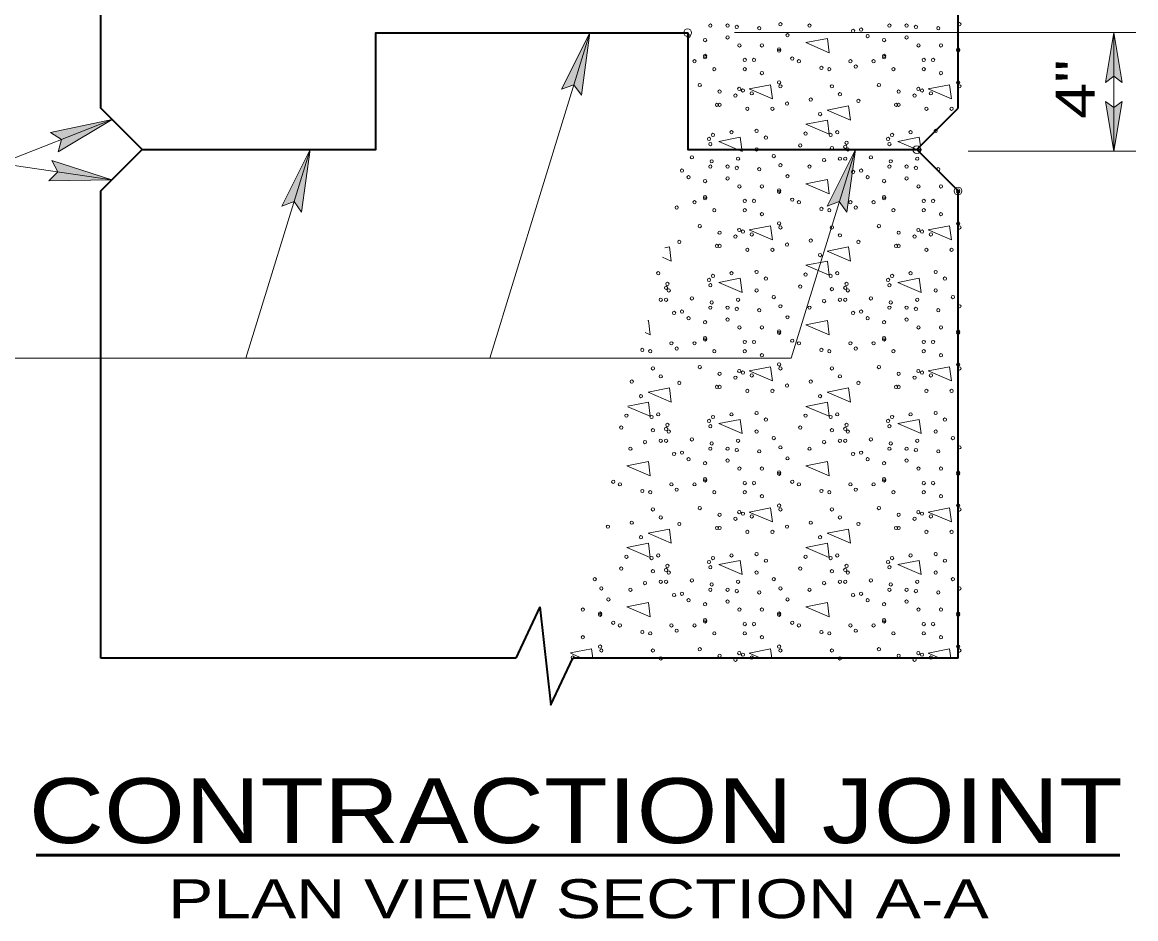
# Model space of a CAD drawing. Extents: x -43.06 to -36.2, y -1.41 to 7.25.
# Drawn here: x -41.643 to -39.928, y 4.85 to 6.232 of the extents above; entities that cross this region are included whole.
import ezdxf
from ezdxf.enums import TextEntityAlignment as Align

# ---------------------------------------------------------------- set-up
doc = ezdxf.new("R2010")
doc.units = 0
doc.header["$LTSCALE"] = 0.024
doc.header["$PDMODE"] = 32
doc.header["$PDSIZE"] = 0.012
for name, color, linetype, lineweight in [('1', 7, 'Continuous', 35), ('10', 7, 'Continuous', 13), ('12', 7, 'Continuous', 53), ('6', 7, 'Continuous', 13)]:
    doc.layers.add(name, color=color, linetype=linetype, lineweight=lineweight)

msp = doc.modelspace()

# ---------------------------------------------------------------- hatches: boundary and pattern name
at = {"layer": '10'}
for points in [[(-40.78142, 6.11917), (-40.76858, 6.21567), (-40.81208, 6.1285), (-40.79325, 6.13533)], [(-39.94858, 6.13917), (-39.96125, 6.216), (-39.97408, 6.13917), (-39.96125, 6.14867)], [(-39.94858, 6.10983), (-39.96125, 6.033), (-39.97408, 6.10983), (-39.96125, 6.10017)], [(-41.50408, 6.08167), (-41.58758, 6.03183), (-41.58225, 6.05117), (-41.59925, 6.06167)], [(-41.19942, 6.0355), (-41.21242, 5.939), (-41.22408, 5.95533), (-41.24292, 5.9485)], [(-40.35958, 6.0355), (-40.37258, 5.939), (-40.38442, 5.95533), (-40.40325, 5.9485)], [(-41.50458, 5.98883), (-41.59725, 6.01883), (-41.58775, 6.00117), (-41.60192, 5.98717)]]:
    msp.add_hatch(color=256, dxfattribs=at).paths.add_polyline_path(points)

# ---------------------------------------------------------------- linework, layer by layer
at = {"layer": '1'}
for p, q in [((-41.52158, 6.09917), (-41.52158, 6.76683)), ((-40.20142, 6.09917), (-40.20142, 6.76583)), ((-40.26492, 6.0355), (-40.20142, 6.09917)), ((-40.20142, 5.97183), (-40.26492, 6.0355)), ((-40.20142, 5.25183), (-40.20142, 5.97183))]:
    msp.add_line(p, q, dxfattribs=at)
for points in [[(-41.45792, 6.0355), (-41.09792, 6.0355), (-41.09792, 6.21567), (-40.61775, 6.21567)], [(-40.61775, 6.21567), (-40.61775, 6.0355), (-40.25775, 6.0355)], [(-41.52158, 5.25183), (-41.52158, 5.97183), (-41.45792, 6.0355), (-41.52158, 6.09917)]]:
    msp.add_lwpolyline(points, dxfattribs=at)
at = {"layer": '10'}
for p, q in [((-40.92258, 5.71433), (-40.76858, 6.21567)), ((-40.81208, 6.1285), (-40.76858, 6.21567)), ((-40.78142, 6.11917), (-40.76858, 6.21567)), ((-39.97408, 6.13917), (-39.96125, 6.216)), ((-39.96125, 6.033), (-39.96125, 6.216)), ((-39.94858, 6.13917), (-39.96125, 6.216)), ((-39.97408, 6.13917), (-39.96125, 6.14867)), ((-39.94858, 6.13917), (-39.96125, 6.14867)), ((-40.81208, 6.1285), (-40.79325, 6.13533)), ((-40.78142, 6.11917), (-40.79325, 6.13533)), ((-39.97408, 6.10983), (-39.96125, 6.033)), ((-39.97408, 6.10983), (-39.96125, 6.10017)), ((-39.94858, 6.10983), (-39.96125, 6.033)), ((-39.94858, 6.10983), (-39.96125, 6.10017)), ((-41.67608, 6.01433), (-41.50408, 6.08167)), ((-41.59925, 6.06167), (-41.50408, 6.08167)), ((-41.58758, 6.03183), (-41.50408, 6.08167)), ((-41.59925, 6.06167), (-41.58225, 6.05117)), ((-41.58758, 6.03183), (-41.58225, 6.05117)), ((-41.29825, 5.71433), (-41.19942, 6.0355)), ((-41.24292, 5.9485), (-41.19942, 6.0355)), ((-41.21242, 5.939), (-41.19942, 6.0355)), ((-40.45842, 5.71433), (-40.35958, 6.0355)), ((-40.40325, 5.9485), (-40.35958, 6.0355)), ((-40.37258, 5.939), (-40.35958, 6.0355)), ((-40.18575, 6.033), (-39.92775, 6.033)), ((-41.67608, 6.01433), (-41.50458, 5.98883)), ((-41.59725, 6.01883), (-41.50458, 5.98883)), ((-41.59725, 6.01883), (-41.58775, 6.00117)), ((-41.60192, 5.98717), (-41.58775, 6.00117)), ((-41.60192, 5.98717), (-41.50458, 5.98883)), ((-41.24292, 5.9485), (-41.22408, 5.95533)), ((-41.21242, 5.939), (-41.22408, 5.95533)), ((-40.40325, 5.9485), (-40.38442, 5.95533)), ((-40.37258, 5.939), (-40.38442, 5.95533)), ((-41.76292, 5.71433), (-41.29825, 5.71433)), ((-41.30158, 5.71433), (-40.91175, 5.71433)), ((-40.92258, 5.71433), (-40.45842, 5.71433))]:
    msp.add_line(p, q, dxfattribs=at)
at = {"layer": '10', "lineweight": 35}
for p, q in [((-40.84558, 5.33083), (-40.88242, 5.25183)), ((-40.88242, 5.25183), (-41.52158, 5.25183)), ((-40.20142, 5.25183), (-40.79458, 5.25183))]:
    msp.add_line(p, q, dxfattribs=at)
at = {"layer": '10'}
for points in [[(-40.78142, 6.11917), (-40.76858, 6.21567), (-40.81208, 6.1285), (-40.79325, 6.13533)], [(-39.94858, 6.13917), (-39.96125, 6.216), (-39.97408, 6.13917), (-39.96125, 6.14867)], [(-39.94858, 6.10983), (-39.96125, 6.033), (-39.97408, 6.10983), (-39.96125, 6.10017)], [(-41.50408, 6.08167), (-41.58758, 6.03183), (-41.58225, 6.05117), (-41.59925, 6.06167)], [(-41.19942, 6.0355), (-41.21242, 5.939), (-41.22408, 5.95533), (-41.24292, 5.9485)], [(-40.35958, 6.0355), (-40.37258, 5.939), (-40.38442, 5.95533), (-40.40325, 5.9485)], [(-41.50458, 5.98883), (-41.59725, 6.01883), (-41.58775, 6.00117), (-41.60192, 5.98717)]]:
    msp.add_lwpolyline(points, close=True, dxfattribs=at)
msp.add_lwpolyline([(-40.54575, 6.216), (-40.10742, 6.216), (-39.92775, 6.216)], dxfattribs=at)
at = {"layer": '10', "lineweight": 35}
msp.add_lwpolyline([(-40.84558, 5.33083), (-40.82875, 5.17983), (-40.79458, 5.25183)], dxfattribs=at)
at = {"layer": '12'}
msp.add_line((-41.62142, 4.94817), (-39.95208, 4.94817), dxfattribs=at)
at = {"layer": '6'}
for p, q in [((-40.26492, 6.0355), (-40.29425, 6.04817)), ((-40.78075, 5.25183), (-40.79858, 5.2595)), ((-40.50492, 5.25183), (-40.52325, 5.25967)), ((-40.22925, 5.25183), (-40.24758, 5.25967))]:
    msp.add_line(p, q, dxfattribs=at)
for points in [[(-40.43575, 6.20033), (-40.40258, 6.20683), (-40.39975, 6.18483)], [(-40.52325, 6.129), (-40.49025, 6.1355), (-40.48742, 6.11367)], [(-40.24758, 6.129), (-40.21442, 6.1355), (-40.21158, 6.11367)], [(-40.40325, 6.0965), (-40.37008, 6.103), (-40.36725, 6.081)], [(-40.43575, 6.0745), (-40.40258, 6.081), (-40.39975, 6.05917)], [(-40.57008, 6.04817), (-40.53708, 6.0545), (-40.53408, 6.03267)], [(-40.43575, 5.983), (-40.40258, 5.9895), (-40.39975, 5.9675)], [(-40.52325, 5.91167), (-40.49025, 5.91817), (-40.48742, 5.89633)], [(-40.24758, 5.91167), (-40.21442, 5.91817), (-40.21158, 5.89633)], [(-40.40325, 5.87917), (-40.37008, 5.8855), (-40.36725, 5.86367)], [(-40.43575, 5.85717), (-40.40258, 5.86367), (-40.39975, 5.84183)], [(-40.57008, 5.83067), (-40.53708, 5.83717), (-40.53408, 5.81533)], [(-40.29425, 5.83067), (-40.26125, 5.83717), (-40.25842, 5.81533)], [(-40.43575, 5.76567), (-40.40258, 5.772), (-40.39975, 5.75017)], [(-40.52325, 5.69433), (-40.49025, 5.70083), (-40.48742, 5.679)], [(-40.24758, 5.69433), (-40.21442, 5.70083), (-40.21158, 5.679)], [(-40.67892, 5.66167), (-40.64592, 5.66817), (-40.64308, 5.64633)], [(-40.40325, 5.66167), (-40.37008, 5.66817), (-40.36725, 5.64633)], [(-40.43575, 5.63983), (-40.40258, 5.64633), (-40.39975, 5.6245)], [(-40.57008, 5.61333), (-40.53708, 5.61983), (-40.53408, 5.598)], [(-40.29425, 5.61333), (-40.26125, 5.61983), (-40.25842, 5.598)], [(-40.71158, 5.54817), (-40.67842, 5.55467), (-40.67558, 5.53283)], [(-40.43575, 5.54817), (-40.40258, 5.55467), (-40.39975, 5.53283)], [(-40.52325, 5.477), (-40.49025, 5.4835), (-40.48742, 5.46167)], [(-40.24758, 5.477), (-40.21442, 5.4835), (-40.21158, 5.46167)], [(-40.67892, 5.44433), (-40.64592, 5.45083), (-40.64308, 5.429)], [(-40.40325, 5.44433), (-40.37008, 5.45083), (-40.36725, 5.429)], [(-40.71158, 5.4225), (-40.67842, 5.429), (-40.67558, 5.40717)], [(-40.43575, 5.4225), (-40.40258, 5.429), (-40.39975, 5.40717)], [(-40.57008, 5.396), (-40.53708, 5.4025), (-40.53408, 5.38067)], [(-40.29425, 5.396), (-40.26125, 5.4025), (-40.25842, 5.38067)], [(-40.71158, 5.33083), (-40.67842, 5.33733), (-40.67558, 5.3155)], [(-40.43575, 5.33083), (-40.40258, 5.33733), (-40.39975, 5.3155)]]:
    msp.add_lwpolyline(points, close=True, dxfattribs=at)
for points in [[(-40.29425, 6.04817), (-40.26125, 6.0545), (-40.25942, 6.04117)], [(-40.65308, 5.88417), (-40.64592, 5.8855), (-40.64308, 5.86367), (-40.65642, 5.8695)], [(-40.67925, 5.772), (-40.67842, 5.772), (-40.67558, 5.75017), (-40.68342, 5.75367)], [(-40.70992, 5.64017), (-40.67842, 5.64633), (-40.67558, 5.6245), (-40.71008, 5.63933)], [(-40.79842, 5.25983), (-40.76608, 5.26617), (-40.76408, 5.25183)], [(-40.52325, 5.25967), (-40.49025, 5.26617), (-40.48842, 5.25183)], [(-40.24758, 5.25967), (-40.21442, 5.26617), (-40.21258, 5.25183)]]:
    msp.add_lwpolyline(points, dxfattribs=at)
for centre in [(-40.58293, 6.22667), (-40.55644, 6.22667), (-40.5422, 6.22463), (-40.47503, 6.22872), (-40.43022, 6.22667), (-40.30712, 6.22667), (-40.28064, 6.22667), (-40.2664, 6.22463), (-40.19923, 6.22872), (-40.61645, 6.21039), (-40.55644, 6.20835), (-40.5076, 6.22259), (-40.46411, 6.21179), (-40.36305, 6.21851), (-40.35081, 6.22055), (-40.34065, 6.21039), (-40.28064, 6.20835), (-40.23179, 6.22259), (-40.59105, 6.20427), (-40.53812, 6.19611), (-40.50351, 6.19611), (-40.47703, 6.19003), (-40.31524, 6.20427), (-40.26232, 6.19611), (-40.22771, 6.19611), (-40.20123, 6.19003), (-40.60733, 6.17171), (-40.59105, 6.17983), (-40.59105, 6.17779), (-40.53, 6.17375), (-40.51572, 6.17375), (-40.47703, 6.18799), (-40.45671, 6.17575), (-40.44651, 6.17171), (-40.36709, 6.17171), (-40.33153, 6.17171), (-40.31524, 6.17983), (-40.31524, 6.17779), (-40.2542, 6.17375), (-40.23991, 6.17375), (-40.20123, 6.18799), (-40.57681, 6.15946), (-40.53, 6.15946), (-40.4119, 6.1615), (-40.3997, 6.15946), (-40.35897, 6.16354), (-40.301, 6.15946), (-40.2542, 6.15946), (-40.50351, 6.15338), (-40.47703, 6.1391), (-40.22771, 6.15338), (-40.20123, 6.1391), (-40.59921, 6.13506), (-40.56869, 6.12486), (-40.53836, 6.12902), (-40.53272, 6.12658), (-40.51908, 6.12222), (-40.47503, 6.13302), (-40.39562, 6.13302), (-40.38342, 6.12078), (-40.32341, 6.13506), (-40.29288, 6.12486), (-40.26256, 6.12902), (-40.25692, 6.12658), (-40.24327, 6.12222), (-40.19923, 6.13302), (-40.57273, 6.1045), (-40.56869, 6.1045), (-40.54424, 6.11878), (-40.46483, 6.10654), (-40.42818, 6.11266), (-40.35489, 6.11062), (-40.29692, 6.1045), (-40.29288, 6.1045), (-40.26844, 6.11878), (-40.52592, 6.09841), (-40.48723, 6.09841), (-40.41394, 6.09025), (-40.25011, 6.09841), (-40.21143, 6.09841), (-40.58497, 6.05205), (-40.57885, 6.05817), (-40.55036, 6.06225), (-40.51168, 6.06429), (-40.49739, 6.05409), (-40.43634, 6.06021), (-40.39766, 6.05817), (-40.38746, 6.06225), (-40.30916, 6.05205), (-40.30304, 6.05817), (-40.27456, 6.06225), (-40.23587, 6.06429), (-40.58293, 6.04393), (-40.51168, 6.03576), (-40.44447, 6.04189), (-40.39562, 6.0378), (-40.37525, 6.03985), (-40.37321, 6.04597), (-40.37117, 6.03576), (-40.30712, 6.04393), (-40.61141, 6.02356), (-40.58089, 6.01744), (-40.54016, 6.02152), (-40.48519, 6.0256), (-40.40782, 6.01948), (-40.38342, 6.02152), (-40.37525, 6.02152), (-40.33561, 6.02356), (-40.30508, 6.01744), (-40.26436, 6.02152), (-40.62661, 6.0032), (-40.58293, 6.00932), (-40.55644, 6.00932), (-40.5422, 6.00728), (-40.5076, 6.00524), (-40.47503, 6.01136), (-40.43022, 6.00932), (-40.36305, 6.00116), (-40.35081, 6.0032), (-40.30712, 6.00932), (-40.28064, 6.00932), (-40.2664, 6.00728), (-40.23179, 6.00524), (-40.61645, 5.99304), (-40.59105, 5.98692), (-40.55644, 5.991), (-40.46411, 5.99444), (-40.34065, 5.99304), (-40.31524, 5.98692), (-40.28064, 5.991), (-40.53812, 5.97876), (-40.50351, 5.97876), (-40.47703, 5.97267), (-40.47703, 5.97063), (-40.26232, 5.97876), (-40.22771, 5.97876), (-40.20123, 5.97267), (-40.20123, 5.97063), (-40.60733, 5.95435), (-40.59105, 5.96247), (-40.59105, 5.96043), (-40.53, 5.95639), (-40.51572, 5.95639), (-40.45671, 5.95839), (-40.44651, 5.95435), (-40.36709, 5.95435), (-40.33153, 5.95435), (-40.31524, 5.96247), (-40.31524, 5.96043), (-40.2542, 5.95639), (-40.23991, 5.95639), (-40.63478, 5.94619), (-40.57681, 5.94211), (-40.53, 5.94211), (-40.50351, 5.93603), (-40.4119, 5.94415), (-40.3997, 5.94211), (-40.35897, 5.94619), (-40.301, 5.94211), (-40.2542, 5.94211), (-40.22771, 5.93603), (-40.59921, 5.91771), (-40.47703, 5.92175), (-40.47503, 5.91567), (-40.39562, 5.91567), (-40.32341, 5.91771), (-40.20123, 5.92175), (-40.19923, 5.91567), (-40.56869, 5.9075), (-40.54424, 5.90142), (-40.53836, 5.91166), (-40.53272, 5.90922), (-40.51908, 5.90486), (-40.38342, 5.90342), (-40.29288, 5.9075), (-40.26844, 5.90142), (-40.26256, 5.91166), (-40.25692, 5.90922), (-40.24327, 5.90486), (-40.6307, 5.89326), (-40.57273, 5.88714), (-40.56869, 5.88714), (-40.52592, 5.88106), (-40.48723, 5.88106), (-40.46483, 5.88918), (-40.42818, 5.8953), (-40.35489, 5.89326), (-40.29692, 5.88714), (-40.29288, 5.88714), (-40.25011, 5.88106), (-40.21143, 5.88106), (-40.41394, 5.8729), (-40.51168, 5.84693), (-40.23587, 5.84693), (-40.66326, 5.84489), (-40.64902, 5.82861), (-40.58497, 5.83469), (-40.57885, 5.84081), (-40.55036, 5.84489), (-40.49739, 5.83673), (-40.43634, 5.84285), (-40.39766, 5.84081), (-40.38746, 5.84489), (-40.37321, 5.82861), (-40.30916, 5.83469), (-40.30304, 5.84081), (-40.27456, 5.84489), (-40.22159, 5.83673), (-40.65106, 5.82249), (-40.64698, 5.81841), (-40.58293, 5.82657), (-40.51168, 5.81841), (-40.44447, 5.82453), (-40.39562, 5.82045), (-40.37525, 5.82249), (-40.37117, 5.81841), (-40.30712, 5.82657), (-40.23587, 5.81841), (-40.65922, 5.80417), (-40.65106, 5.80417), (-40.61141, 5.80621), (-40.58089, 5.80009), (-40.54016, 5.80417), (-40.48519, 5.80825), (-40.40782, 5.80213), (-40.38342, 5.80417), (-40.37525, 5.80417), (-40.33561, 5.80621), (-40.30508, 5.80009), (-40.26436, 5.80417), (-40.20939, 5.80825), (-40.63886, 5.7838), (-40.62661, 5.78584), (-40.58293, 5.79197), (-40.55644, 5.79197), (-40.5422, 5.78993), (-40.5076, 5.78788), (-40.47503, 5.79401), (-40.46411, 5.77708), (-40.43022, 5.79197), (-40.36305, 5.7838), (-40.35081, 5.78584), (-40.30712, 5.79197), (-40.28064, 5.79197), (-40.2664, 5.78993), (-40.23179, 5.78788), (-40.19923, 5.79401), (-40.61645, 5.77568), (-40.59105, 5.76956), (-40.55644, 5.77364), (-40.53812, 5.7614), (-40.50351, 5.7614), (-40.34065, 5.77568), (-40.31524, 5.76956), (-40.28064, 5.77364), (-40.26232, 5.7614), (-40.22771, 5.7614), (-40.59105, 5.74512), (-40.59105, 5.74308), (-40.47703, 5.75532), (-40.47703, 5.75328), (-40.31524, 5.74512), (-40.31524, 5.74308), (-40.20123, 5.75532), (-40.20123, 5.75328), (-40.6877, 5.72679), (-40.6429, 5.737), (-40.63478, 5.72884), (-40.60733, 5.737), (-40.53, 5.73904), (-40.51572, 5.73904), (-40.45671, 5.74104), (-40.44651, 5.737), (-40.4119, 5.72679), (-40.36709, 5.737), (-40.35897, 5.72884), (-40.33153, 5.737), (-40.2542, 5.73904), (-40.23991, 5.73904), (-40.6755, 5.72475), (-40.57681, 5.72475), (-40.53, 5.72475), (-40.50351, 5.71867), (-40.3997, 5.72475), (-40.301, 5.72475), (-40.2542, 5.72475), (-40.22771, 5.71867), (-40.67142, 5.69831), (-40.59921, 5.70035), (-40.53836, 5.69431), (-40.53272, 5.69187), (-40.47703, 5.70439), (-40.47503, 5.69831), (-40.39562, 5.69831), (-40.32341, 5.70035), (-40.26256, 5.69431), (-40.25692, 5.69187), (-40.20123, 5.70439), (-40.19923, 5.69831), (-40.70399, 5.67795), (-40.65922, 5.68607), (-40.6307, 5.67591), (-40.56869, 5.69015), (-40.54424, 5.68407), (-40.51908, 5.68751), (-40.42818, 5.67795), (-40.38342, 5.68607), (-40.35489, 5.67591), (-40.29288, 5.69015), (-40.26844, 5.68407), (-40.24327, 5.68751), (-40.57273, 5.66979), (-40.56869, 5.66979), (-40.52592, 5.6637), (-40.48723, 5.6637), (-40.46483, 5.67183), (-40.29692, 5.66979), (-40.29288, 5.66979), (-40.25011, 5.6637), (-40.21143, 5.6637), (-40.68974, 5.65554), (-40.41394, 5.65554), (-40.71215, 5.6255), (-40.67346, 5.62346), (-40.66326, 5.62754), (-40.57885, 5.62346), (-40.55036, 5.62754), (-40.51168, 5.62958), (-40.43634, 5.6255), (-40.39766, 5.62346), (-40.38746, 5.62754), (-40.30304, 5.62346), (-40.27456, 5.62754), (-40.23587, 5.62958), (-40.72027, 5.60718), (-40.64902, 5.61126), (-40.58497, 5.61734), (-40.58293, 5.60922), (-40.49739, 5.61938), (-40.44447, 5.60718), (-40.37321, 5.61126), (-40.30916, 5.61734), (-40.30712, 5.60922), (-40.22159, 5.61938), (-40.67142, 5.6031), (-40.65106, 5.60514), (-40.64698, 5.60105), (-40.61141, 5.58885), (-40.51168, 5.60105), (-40.48519, 5.59089), (-40.39562, 5.6031), (-40.37525, 5.60514), (-40.37117, 5.60105), (-40.33561, 5.58885), (-40.23587, 5.60105), (-40.20939, 5.59089), (-40.70603, 5.57461), (-40.68362, 5.58477), (-40.65922, 5.58681), (-40.65106, 5.58681), (-40.58293, 5.57461), (-40.58089, 5.58273), (-40.55644, 5.57461), (-40.5422, 5.57257), (-40.54016, 5.58681), (-40.47503, 5.57665), (-40.43022, 5.57461), (-40.40782, 5.58477), (-40.38342, 5.58681), (-40.37525, 5.58681), (-40.30712, 5.57461), (-40.30508, 5.58273), (-40.28064, 5.57461), (-40.2664, 5.57257), (-40.26436, 5.58681), (-40.19923, 5.57665), (-40.63886, 5.56645), (-40.62661, 5.56849), (-40.61645, 5.55833), (-40.55644, 5.55629), (-40.5076, 5.57053), (-40.46411, 5.55973), (-40.36305, 5.56645), (-40.35081, 5.56849), (-40.34065, 5.55833), (-40.28064, 5.55629), (-40.23179, 5.57053), (-40.59105, 5.55221), (-40.53812, 5.54405), (-40.50351, 5.54405), (-40.47703, 5.53796), (-40.31524, 5.55221), (-40.26232, 5.54405), (-40.22771, 5.54405), (-40.20123, 5.53796), (-40.73251, 5.52368), (-40.59105, 5.52776), (-40.59105, 5.52572), (-40.53, 5.52168), (-40.51572, 5.52168), (-40.47703, 5.53592), (-40.45671, 5.52368), (-40.31524, 5.52776), (-40.31524, 5.52572), (-40.2542, 5.52168), (-40.23991, 5.52168), (-40.20123, 5.53592), (-40.72231, 5.51964), (-40.6877, 5.50944), (-40.6755, 5.5074), (-40.6429, 5.51964), (-40.63478, 5.51148), (-40.60733, 5.51964), (-40.57681, 5.5074), (-40.53, 5.5074), (-40.44651, 5.51964), (-40.4119, 5.50944), (-40.3997, 5.5074), (-40.36709, 5.51964), (-40.35897, 5.51148), (-40.33153, 5.51964), (-40.301, 5.5074), (-40.2542, 5.5074), (-40.50351, 5.50132), (-40.47703, 5.48704), (-40.22771, 5.50132), (-40.20123, 5.48704), (-40.67142, 5.48096), (-40.65922, 5.46871), (-40.59921, 5.483), (-40.56869, 5.47279), (-40.53836, 5.47695), (-40.53272, 5.47451), (-40.51908, 5.47015), (-40.47503, 5.48096), (-40.39562, 5.48096), (-40.38342, 5.46871), (-40.32341, 5.483), (-40.29288, 5.47279), (-40.26256, 5.47695), (-40.25692, 5.47451), (-40.24327, 5.47015), (-40.19923, 5.48096), (-40.74063, 5.45447), (-40.70399, 5.46059), (-40.6307, 5.45855), (-40.57273, 5.45243), (-40.56869, 5.45243), (-40.54424, 5.46671), (-40.46483, 5.45447), (-40.42818, 5.46059), (-40.35489, 5.45855), (-40.29692, 5.45243), (-40.29288, 5.45243), (-40.26844, 5.46671), (-40.68974, 5.43819), (-40.52592, 5.44635), (-40.48723, 5.44635), (-40.41394, 5.43819), (-40.25011, 5.44635), (-40.21143, 5.44635), (-40.71215, 5.40814), (-40.67346, 5.4061), (-40.66326, 5.41018), (-40.58497, 5.39998), (-40.57885, 5.4061), (-40.55036, 5.41018), (-40.51168, 5.41222), (-40.49739, 5.40202), (-40.43634, 5.40814), (-40.39766, 5.4061), (-40.38746, 5.41018), (-40.30916, 5.39998), (-40.30304, 5.4061), (-40.27456, 5.41018), (-40.23587, 5.41222), (-40.22159, 5.40202), (-40.72027, 5.38982), (-40.67142, 5.38574), (-40.65106, 5.38778), (-40.64902, 5.3939), (-40.64698, 5.3837), (-40.58293, 5.39186), (-40.51168, 5.3837), (-40.44447, 5.38982), (-40.39562, 5.38574), (-40.37525, 5.38778), (-40.37321, 5.3939), (-40.37117, 5.3837), (-40.30712, 5.39186), (-40.23587, 5.3837), (-40.761, 5.37354), (-40.68362, 5.36742), (-40.65922, 5.36946), (-40.65106, 5.36946), (-40.61141, 5.3715), (-40.58089, 5.36538), (-40.54016, 5.36946), (-40.48519, 5.37354), (-40.40782, 5.36742), (-40.38342, 5.36946), (-40.37525, 5.36946), (-40.33561, 5.3715), (-40.30508, 5.36538), (-40.26436, 5.36946), (-40.20939, 5.37354), (-40.75083, 5.3593), (-40.70603, 5.35726), (-40.63886, 5.34909), (-40.62661, 5.35113), (-40.58293, 5.35726), (-40.55644, 5.35726), (-40.5422, 5.35522), (-40.5076, 5.35318), (-40.47503, 5.3593), (-40.43022, 5.35726), (-40.36305, 5.34909), (-40.35081, 5.35113), (-40.30712, 5.35726), (-40.28064, 5.35726), (-40.2664, 5.35522), (-40.23179, 5.35318), (-40.19923, 5.3593), (-40.73991, 5.34237), (-40.61645, 5.34097), (-40.59105, 5.33485), (-40.55644, 5.33893), (-40.46411, 5.34237), (-40.34065, 5.34097), (-40.31524, 5.33485), (-40.28064, 5.33893), (-40.77932, 5.32669), (-40.75283, 5.32061), (-40.75283, 5.31857), (-40.53812, 5.32669), (-40.50351, 5.32669), (-40.47703, 5.32061), (-40.47703, 5.31857), (-40.26232, 5.32669), (-40.22771, 5.32669), (-40.20123, 5.32061), (-40.20123, 5.31857), (-40.73251, 5.30633), (-40.72231, 5.30229), (-40.6429, 5.30229), (-40.60733, 5.30229), (-40.59105, 5.31041), (-40.59105, 5.30837), (-40.53, 5.30433), (-40.51572, 5.30433), (-40.45671, 5.30633), (-40.44651, 5.30229), (-40.36709, 5.30229), (-40.33153, 5.30229), (-40.31524, 5.31041), (-40.31524, 5.30837), (-40.2542, 5.30433), (-40.23991, 5.30433), (-40.77932, 5.28396), (-40.6877, 5.29209), (-40.6755, 5.29005), (-40.63478, 5.29413), (-40.57681, 5.29005), (-40.53, 5.29005), (-40.50351, 5.28396), (-40.4119, 5.29209), (-40.3997, 5.29005), (-40.35897, 5.29413), (-40.301, 5.29005), (-40.2542, 5.29005), (-40.22771, 5.28396), (-40.75283, 5.26968), (-40.75083, 5.2636), (-40.67142, 5.2636), (-40.59921, 5.26564), (-40.47703, 5.26968), (-40.47503, 5.2636), (-40.39562, 5.2636), (-40.32341, 5.26564), (-40.20123, 5.26968), (-40.19923, 5.2636), (-40.79488, 5.2528), (-40.65922, 5.25136), (-40.56869, 5.25544), (-40.54424, 5.24936), (-40.53836, 5.2596), (-40.53272, 5.25716), (-40.51908, 5.2528), (-40.38342, 5.25136), (-40.29288, 5.25544), (-40.26844, 5.24936), (-40.26256, 5.2596), (-40.25692, 5.25716), (-40.24327, 5.2528)]:
    msp.add_circle(centre, 0.00252, dxfattribs=at)
for p in [(-40.61775, 6.21567), (-40.26492, 6.0355), (-40.20142, 5.97183)]:
    msp.add_point(p, dxfattribs=at)

# ---------------------------------------------------------------- texts
at = {"layer": '12', "width": 1.25}
msp.add_text('4"', height=0.06001, rotation=90, dxfattribs=at).set_placement((-39.99125, 6.12862), align=Align.CENTER)
at = {"layer": '12'}
for s, height, width, p in [('CONTRACTION JOINT', 0.1, 1.2, (-40.79025, 4.96683)), ('PLAN VIEW SECTION A-A', 0.06001, 1.3, (-40.78612, 4.85108))]:
    msp.add_text(s, height=height, dxfattribs=dict(at, width=width)).set_placement(p, align=Align.CENTER)

doc.saveas('drawing.dxf')
